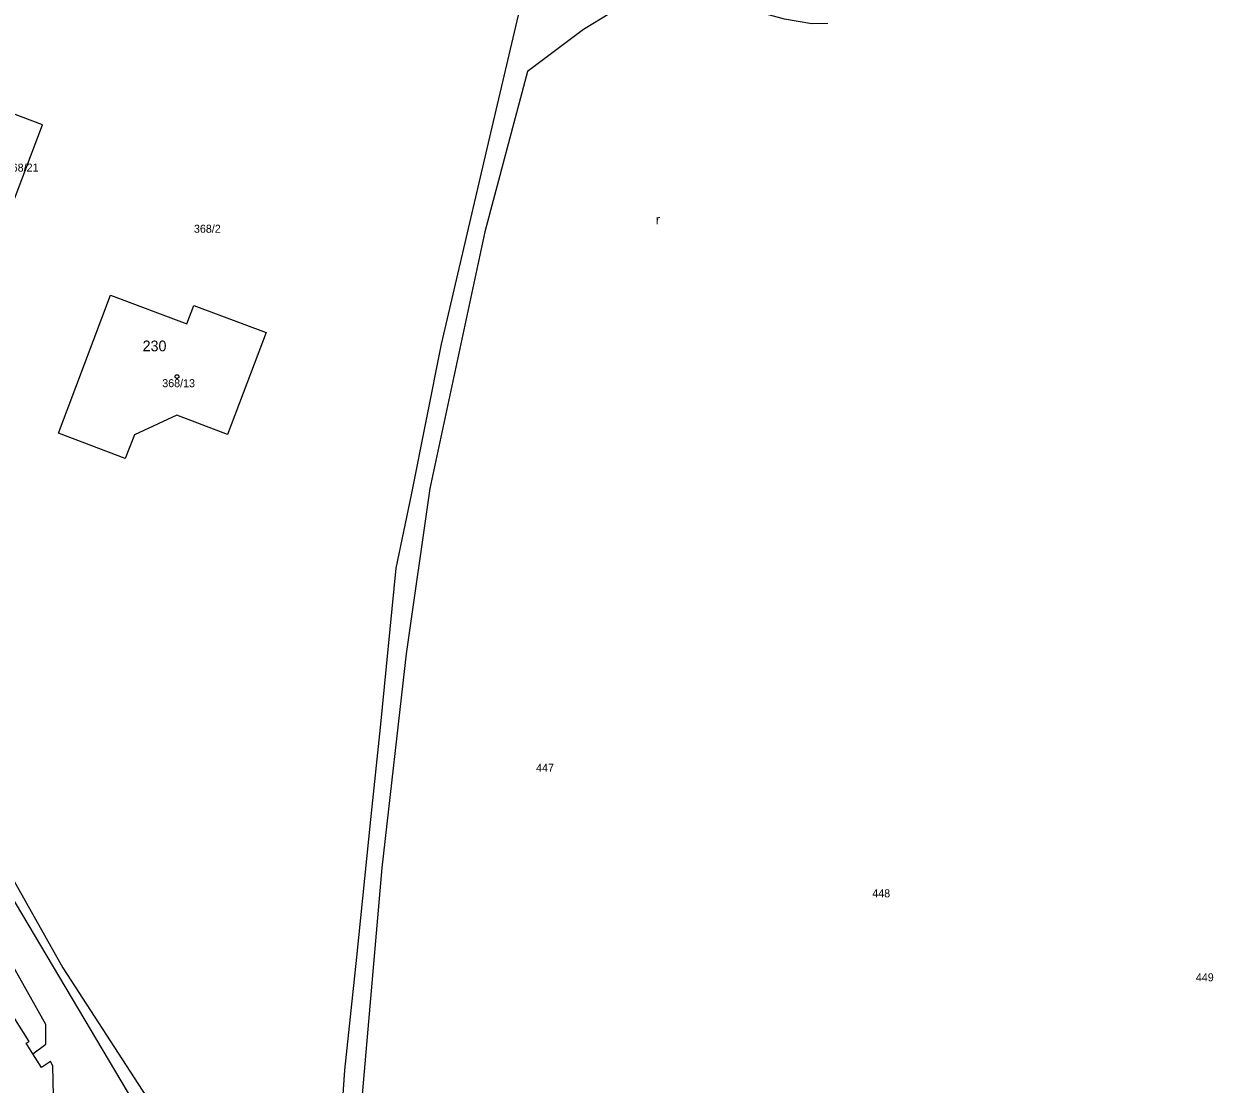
# Model space of a CAD drawing. Extents: x -836739 to -835945, y -1070775 to -1070126.
# Drawn here: x -836458 to -836346.5, y -1070547.4 to -1070448 of the extents above; entities that cross this region are included whole.
import ezdxf

# ---------------------------------------------------------------- set-up
doc = ezdxf.new("R2010")
doc.units = 0
for name, color, linetype in [('BodPole_mer', 7, 'Continuous'), ('Budovy_hranice', 7, 'Continuous'), ('Budovy_kody', 7, 'Continuous'), ('Doprava_hranice', 7, 'Continuous'), ('OstPloch_hranice', 7, 'Continuous'), ('OstPloch_kody', 7, 'Continuous'), ('RuianAdr_popis', 7, 'Continuous'), ('RuianPar_popis', 7, 'Continuous'), ('Stavby_linie', 7, 'Continuous')]:
    doc.layers.add(name, color=color, linetype=linetype)

msp = doc.modelspace()

# ---------------------------------------------------------------- linework, layer by layer
at = {"layer": 'BodPole_mer'}
for p, q in [((-836405.51, -1070448.52), (-836405.51, -1070448.52)), ((-836384.12, -1070448.01), (-836384.12, -1070448.01)), ((-836410.77, -1070452.46), (-836410.77, -1070452.46)), ((-836456.23, -1070457.47), (-836456.23, -1070457.47)), ((-836414.08, -1070457.69), (-836414.08, -1070457.69)), ((-836414.78, -1070467.48), (-836414.78, -1070467.48)), ((-836449.84, -1070473.42), (-836449.84, -1070473.42)), ((-836442.03, -1070474.39), (-836442.03, -1070474.39)), ((-836442.69, -1070476.12), (-836442.69, -1070476.12)), ((-836435.26, -1070476.94), (-836435.26, -1070476.94)), ((-836418.84, -1070478.02), (-836418.84, -1070478.02)), ((-836443.65, -1070484.69), (-836443.65, -1070484.69)), ((-836454.72, -1070486.36), (-836454.72, -1070486.36)), ((-836447.6, -1070486.53), (-836447.6, -1070486.53)), ((-836438.88, -1070486.49), (-836438.88, -1070486.49)), ((-836448.47, -1070488.73), (-836448.47, -1070488.73)), ((-836421.63, -1070492.15), (-836421.63, -1070492.15)), ((-836419.92, -1070491.57), (-836419.92, -1070491.57)), ((-836423.07, -1070499.04), (-836423.07, -1070499.04)), ((-836422.14, -1070507.07), (-836422.14, -1070507.07)), ((-836424.54, -1070513.97), (-836424.54, -1070513.97)), ((-836425.46, -1070522.59), (-836425.46, -1070522.59)), ((-836424.43, -1070527.13), (-836424.43, -1070527.13)), ((-836426.76, -1070535.49), (-836426.76, -1070535.49)), ((-836454.31, -1070536.5), (-836454.31, -1070536.5)), ((-836455.92, -1070541.81), (-836455.92, -1070541.81)), ((-836457.76, -1070543.56), (-836457.76, -1070543.56)), ((-836457.47, -1070543.39), (-836457.47, -1070543.39)), ((-836455.91, -1070543.66), (-836455.91, -1070543.66)), ((-836457.12, -1070544.57), (-836457.12, -1070544.57)), ((-836456.33, -1070545.83), (-836456.33, -1070545.83)), ((-836455.47, -1070545.28), (-836455.47, -1070545.28)), ((-836455.26, -1070545.68), (-836455.26, -1070545.68)), ((-836427.9, -1070546.1), (-836427.9, -1070546.1))]:
    msp.add_line(p, q, dxfattribs=at)
at = {"layer": 'Budovy_hranice'}
for p, q in [((-836454.72, -1070486.36), (-836449.84, -1070473.42)), ((-836449.84, -1070473.42), (-836442.69, -1070476.12)), ((-836442.69, -1070476.12), (-836442.03, -1070474.39)), ((-836442.03, -1070474.39), (-836435.26, -1070476.94)), ((-836435.26, -1070476.94), (-836438.88, -1070486.49)), ((-836443.65, -1070484.69), (-836447.6, -1070486.53)), ((-836438.88, -1070486.49), (-836443.65, -1070484.69)), ((-836448.47, -1070488.73), (-836454.72, -1070486.36)), ((-836447.6, -1070486.53), (-836448.47, -1070488.73))]:
    msp.add_line(p, q, dxfattribs=at)
msp.add_lwpolyline([(-836456.23, -1070457.47), (-836461.55, -1070455.46), (-836465.35, -1070465.47), (-836460, -1070467.47), (-836456.23, -1070457.47)], dxfattribs=at)
at = {"layer": 'Budovy_kody'}
msp.add_circle((-836443.62, -1070481.07), 0.175, dxfattribs=at)
at = {"layer": 'Doprava_hranice'}
for points in [[(-836457.12, -1070544.57), (-836455.91, -1070543.66), (-836455.92, -1070541.81), (-836461.09, -1070532.63), (-836472.09, -1070514.53), (-836483.11, -1070498.19), (-836497.22, -1070479.49), (-836508.79, -1070465.29), (-836511.15, -1070463.33), (-836513.54, -1070462.56), (-836514.44, -1070462.65), (-836514.68, -1070463.85)], [(-836504.94, -1070463.64), (-836487.47, -1070484.91), (-836483.47, -1070489.88), (-836478.99, -1070496.57), (-836476.3, -1070501.37), (-836473.79, -1070505.61), (-836465.77, -1070518.73), (-836447.09, -1070550.1), (-836449.85, -1070551.69), (-836449.97, -1070560.65)]]:
    msp.add_lwpolyline(points, dxfattribs=at)
at = {"layer": 'OstPloch_hranice'}
msp.add_lwpolyline([(-836382.62, -1070447.97), (-836384.12, -1070448.01), (-836386.69, -1070447.56), (-836394.4, -1070445.42), (-836398.28, -1070444.88), (-836400.59, -1070445.48), (-836405.51, -1070448.52), (-836410.77, -1070452.46), (-836414.78, -1070467.48), (-836419.92, -1070491.57), (-836422.14, -1070507.07), (-836424.43, -1070527.13), (-836426.86, -1070555.21), (-836427.73, -1070571.17), (-836426.62, -1070578.67)], dxfattribs=at)
at = {"layer": 'RuianAdr_popis'}
msp.add_line((-836446.84, -1070478.69), (-836446.84, -1070478.69), dxfattribs=at)
at = {"layer": 'RuianPar_popis'}
for p, q in [((-836442.03, -1070467.58), (-836442.03, -1070467.58)), ((-836445, -1070482.06), (-836445, -1070482.06)), ((-836409.96, -1070518.12), (-836409.96, -1070518.12)), ((-836378.45, -1070529.89), (-836378.45, -1070529.89)), ((-836348.12, -1070537.76), (-836348.12, -1070537.76))]:
    msp.add_line(p, q, dxfattribs=at)
at = {"layer": 'Stavby_linie'}
msp.add_line((-836455.14, -1070551.44), (-836455.26, -1070545.68), dxfattribs=at)
for points in [[(-836427.9, -1070546.1), (-836426.76, -1070535.49), (-836425.46, -1070522.59), (-836424.54, -1070513.97), (-836423.07, -1070499.04), (-836421.63, -1070492.15), (-836418.84, -1070478.02), (-836414.08, -1070457.69), (-836411.22, -1070445.56), (-836410.44, -1070442.44), (-836407.72, -1070434.26)], [(-836466.12, -1070515.52), (-836454.31, -1070536.5), (-836429.82, -1070574.29), (-836427.9, -1070546.1)], [(-836457.76, -1070543.56), (-836457.47, -1070543.39), (-836462.88, -1070534.88)], [(-836455.26, -1070545.68), (-836455.47, -1070545.28), (-836456.33, -1070545.83), (-836457.12, -1070544.57), (-836457.76, -1070543.56)]]:
    msp.add_lwpolyline(points, dxfattribs=at)

# ---------------------------------------------------------------- texts
at = {"layer": 'OstPloch_kody'}
msp.add_text('r', height=0.9, dxfattribs=at).set_placement((-836398.74, -1070466.79))
at = {"layer": 'RuianAdr_popis'}
msp.add_text('230', height=1, dxfattribs=at).set_placement((-836446.84, -1070478.69))
at = {"layer": 'RuianPar_popis'}
for s, p in [('368/21', (-836459.67, -1070461.85)), ('368/2', (-836442.03, -1070467.58)), ('368/13', (-836445, -1070482.06)), ('447', (-836409.96, -1070518.12)), ('448', (-836378.45, -1070529.89)), ('449', (-836348.12, -1070537.76))]:
    msp.add_text(s, height=0.75, dxfattribs=at).set_placement(p)

doc.saveas('drawing.dxf')
